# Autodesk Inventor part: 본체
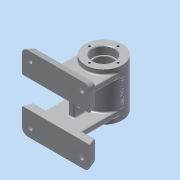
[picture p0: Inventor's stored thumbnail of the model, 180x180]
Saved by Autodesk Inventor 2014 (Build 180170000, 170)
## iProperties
Created: 2016-07
Part Number: 본체
Material: 알루미늄 6061
Document SubType Name: Modeling
Designer: 406-003
Density: 2.71 g/cm^3
Appearance: 알루미늄 - 평지
Author: 406-003
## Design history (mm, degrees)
sketch "스케치1"
  geometry: L1 (100, -55)-(0, -55); L2 (0, -55)-(0, -20); L3 (0, -20)-(100, -20); L4 (100, -20)-(100, -55); L5 (100, 0)-(0, 0); L6 (0, 0)-(0, 55); L7 (0, 55)-(100, 55); L8 (100, 55)-(100, 0); L9 (100, -20)-(100, 0); L10 (0, -20)-(0, 0); 1 further point
  constraints: 20 end point, 4 collinear, 4 parallel, 2 horizontal, 2 perpendicular, 1 coincident, 1 vertical alignment
  dimensions: "d0" = 20 distance between parallel lines of L3 L5; "d1" = 110 distance of L1.end L6.end; "d2" = 35 distance of L1.end L2.end; "d3" = 100 distance of L1.start L1.end
extrude "돌출1" new body sketch "스케치1" distance "d4" = 12; taper "d5" = -20 deg
sketch "스케치3"
  geometry: L1 (-100, 20)-(0, 20); L2 (0, 20)-(0, -20); L3 (0, -20)-(-100, -20); L4 (-100, -20)-(-100, 20); L5 (0, -55)-(-100, -55) reference; L6 (-100, 55)-(0, 55) reference; L7 (-100, -55)-(-100, 55) reference; L8 (0, 55)-(0, -55) reference; 1 further point
  constraints: 8 end point, 2 collinear, 2 parallel, 1 horizontal, 1 perpendicular
  dimensions: "d6" = 35 distance between parallel lines of L5 L3; "d7" = 35 distance between parallel lines of L6 L1
extrude "돌출2" cut sketch "스케치3" distance "d8" = 12; taper "d9" = 0 deg
sketch "스케치4"
  geometry: L1 (0, 0)-(-100, 0) reference; C1 r 27 at (-50, 70); 1 further point
  constraints: 1 centre point, 1 midpoint, 1 vertical alignment
  dimensions: "d10" = 70 distance from line of L1 C1.centre; "d11" = 54 diameter of C1
extrude "돌출3" join sketch "스케치4" stored distance "d12" = 70; taper "d13" = 0 deg
sketch "스케치5"
  geometry: L1 (95.632, -12)-(-4.368, -12) reference; L2 (-4.368, -12)-(0, 0) reference; L3 (0, 0)-(91.265, 0) reference; L4 (91.265, 0)-(95.632, -12) reference; L5 (18.632, 58)-(72.632, 58); L6 (72.632, 58)-(72.632, -12); L7 (72.632, -12)-(18.632, -12); L8 (18.632, -12)-(18.632, 58); 1 further point
  constraints: 8 end point, 2 parallel, 2 vertical, 1 horizontal, 1 horizontal alignment, 1 perpendicular, 1 point on line, 1 other
extrude "돌출4" join sketch "스케치5" distance "d14" = 8; taper "d15" = 0 deg
sketch "스케치6"
  geometry: L1 (95.632, -12)-(-4.368, -12) reference; L2 (0, 0)-(91.265, 0) reference; L3 (91.265, 0)-(95.632, -12) reference; L4 (95.632, -12)-(-4.368, -12) reference; L5 (-4.368, -12)-(0, 0) reference; L6 (18.632, 58)-(72.632, 58); L7 (72.632, 58)-(72.632, -12); L8 (72.632, -12)-(18.632, -12); L9 (18.632, -12)-(18.632, 58); C1 r 27 at (45.632, 58) reference; 1 further point
  constraints: 8 end point, 2 parallel, 2 tangent, 1 coincident, 1 collinear, 1 horizontal, 1 midpoint, 1 perpendicular
extrude "돌출5" join sketch "스케치6" distance "d16" = 8; taper "d17" = 0 deg
node "작업 평면1"
sketch "스케치7"
  geometry: L1 (27, 35)-(-27, 35) reference; C1 r 5 at (0, 13); 2 further points
  constraints: 1 centre point, 1 midpoint, 1 vertical alignment
  dimensions: "d18" = 10 diameter of C1; "d19" = 22 distance of point (0, 35) C1.centre
extrude "돌출6" join sketch "스케치7" distance "d20" = 3; taper "d22" = 0 deg; dims "d21" = 4, "d23" = 0
node "작업 평면3"
sketch "스케치8"
  geometry: L1 (75, -12)-(40, -12) reference; L2 (40, -12)-(40, 31) reference; L3 (40, 31)-(0, 31) reference; L4 (0, 31)-(0, -12) reference; L5 (0, -12)-(-35, -12) reference; L6 (-35, -12)-(-30.632, 0) reference; L7 (-30.632, 0)-(-8, 0) reference; L8 (-8, 0)-(-8, 31) reference; L9 (-8, 31)-(-15, 31) reference; L10 (-15, 31)-(-15, 85) reference; L11 (-15, 85)-(28, 85) reference; L12 (28, 85)-(28, 88) reference; L13 (28, 88)-(38, 88) reference; L14 (38, 88)-(38, 85) reference; L15 (38, 85)-(55, 85) reference; L16 (55, 85)-(55, 31) reference; L17 (55, 31)-(48, 31) reference; L18 (48, 31)-(48, 0) reference; L19 (48, 0)-(70.632, 0) reference; L20 (70.632, 0)-(75, -12) reference; L21 (-15, 58)-(55, 58); L22 (-15, 58)-(-15, 74); L23 (-15, 74)-(-3.3, 74); L24 (-3, 73.7)-(-3, 72); L25 (-3, 72)-(-1, 72); L26 (-1, 72)-(-1, 76); L27 (2, 79)-(38, 79); L28 (41, 76)-(41, 72); L29 (41, 72)-(43, 72); L30 (43, 72)-(43, 73.7); L31 (43.3, 74)-(55, 74); L32 (55, 74)-(55, 58); L33 (55, 58)-(-15, 58); A1 r 0.3 centre (-3.3, 73.7) between (-3, 73.7) and (-3.3, 74); A2 r 0.3 centre (43.3, 73.7) between (43.3, 74) and (43, 73.7); A3 r 3 centre (2, 76) between (2, 79) and (-1, 76); A4 r 3 centre (38, 76) between (41, 76) and (38, 79); 5 further points
  constraints: 26 end point, 10 point on line, 8 point on circle, 8 tangent, 5 parallel, 4 centre point, 4 perpendicular, 3 collinear, 2 equal radius, 2 midpoint
  dimensions: "d24" = 12 distance of L22.end point (-3, 74); "d25" = 42 distance of point (-1, 79) point (41, 79); "d26" = 12 distance of point (43, 74) L31.end; "d27" = 2 distance of L24.end L25.end; "d28" = 32 diameter of L23 L21; "d29" = 28 diameter of L25 L21; "d30" = 32 diameter of L31 L21; "d31" = 42 diameter of L27 L21; "d32" = 0.3 radius of A1; "d33" = 3 radius of A3
  node "절단 모서리 투영3"
sketch "스케치9"
  geometry: L1 (75, -12)-(40, -12) reference; L2 (40, -12)-(40, 31) reference; L3 (40, 31)-(0, 31) reference; L4 (0, 31)-(0, -12) reference; L5 (0, -12)-(-35, -12) reference; L6 (-35, -12)-(-30.632, 0) reference; L7 (-30.632, 0)-(-8, 0) reference; L8 (-8, 0)-(-8, 31) reference; L9 (-8, 31)-(-15, 31) reference; L10 (-15, 31)-(-15, 85) reference; L11 (-15, 85)-(28, 85) reference; L12 (28, 85)-(28, 88) reference; L13 (28, 88)-(38, 88) reference; L14 (38, 88)-(38, 85) reference; L15 (38, 85)-(55, 85) reference; L16 (55, 85)-(55, 31) reference; L17 (55, 31)-(48, 31) reference; L18 (48, 31)-(48, 0) reference; L19 (48, 0)-(70.632, 0) reference; L20 (70.632, 0)-(75, -12) reference; L21 (0, 10)-(40, 10); L22 (40, 10)-(40, 45); L23 (40, 45)-(0, 45); L24 (0, 45)-(0, 10); L25 (12, 20)-(28, 20); L26 (12, 23.5)-(28, 23.5); L27 (28, 16.5)-(12, 16.5); A1 r 3.5 centre (12, 20) between (12, 23.5) and (12, 16.5); A2 r 3.5 centre (28, 20) between (28, 16.5) and (28, 23.5); 3 further points
  constraints: 16 end point, 4 parallel, 4 point on circle, 4 tangent, 2 centre point, 2 midpoint, 1 collinear, 1 horizontal, 1 perpendicular, 1 point on line, 1 vertical alignment
  dimensions: "d34" = 21 distance between parallel lines of L3 L21; "d35" = 35 distance of L23.end L21.start; "d36" = 7 distance between parallel lines of L27 L26; "d37" = 23 dimension on A2 A1; "d38" = 32 distance between parallel lines of L5 L25
extrude "돌출7" join sketch "스케치9" stored distance "d39" = 8; taper "d40" = 0 deg
revolve "회전1" stored, may be unused: angle "d41" = 90 deg
sketch "스케치10"
  geometry: L1 (0, -55)-(-100, -55) reference; L2 (-100, -55)-(-100, -20) reference; 2 further points
  dimensions: "d42" = 12.5 distance from line of L1 point (-87.5, -42.5); "d43" = 12.5 distance from line of L2 point (-87.5, -42.5)
hole "구멍1" sketch "스케치10" at (-87.5, -42.5) diameter "d44" = 6; stored, may be unused: countersink angle "d48" = 90 deg, drill point angle "d50" = 118 deg; dims "d45" = 6, "d46" = 10, "d47" = 4, "d49" = 8
sketch "스케치11" dims "d57" = 42
  geometry: C1 r 16 at (0, 0) reference; C2 r 27 at (0, 0) reference; 3 further points
  constraints: 2 vertical alignment, 1 coincident, 2 other
hole "구멍2" sketch "스케치11" at (0, 21) diameter "d58" = 3.242; stored, may be unused: countersink angle "d62" = 90 deg, drill point angle "d64" = 120 deg; dims "d59" = 8, "d60" = 10, "d61" = 4, "d63" = 10
hole "구멍3" diameter "d70" = 5.188; stored, may be unused: countersink angle "d74" = 90 deg, drill point angle "d76" = 120 deg; dims "d68" = 10, "d69" = 10, "d71" = 30, "d72" = 10, "d73" = 4, "d75" = 30
node "작업 평면4"
sketch "스케치12"
  geometry: L1 (0, 0)-(-15.898, -25.441); L2 (4, -26.702)-(4, -34.5) reference; L3 (4, -34.5)-(-4, -34.5) reference; L4 (-4, -34.5)-(-4, -26.702) reference; L5 (4, -41.5)-(4, -48) reference; L6 (4, -48)-(-4, -48) reference; L7 (-4, -48)-(-4, -41.5) reference; L8 (-4, -41.5)-(4, -41.5) reference; L9 (0, 0)-(0, -21); L10 (-15.898, -25.441)-(-10.809, -28.621); L11 (-10.809, -28.621)-(-7.63, -23.533); L12 (-7.63, -23.533)-(-12.718, -20.353); L13 (-15.898, -25.441)-(-12.718, -20.353); A1 r 27 centre (0, 0) between (4, -26.702) and (-4, -26.702) reference; 2 further points
  constraints: 12 end point, 4 perpendicular, 1 coincident, 1 collinear, 1 point on line, 1 vertical alignment, 1 other
  dimensions: "d78" = 30 distance of L1.start L1.end; "d79" = 328 deg dimension on L9 L1; "d80" = 6 distance of L1.end L10.end; "d81" = 6 distance of L10.end L11.end
revolve "회전2" sketch "스케치12" stored, may be unused: angle "d82" = 90 deg
hole "구멍4" diameter "d85" = 5.188; stored, may be unused: countersink angle "d89" = 90 deg, drill point angle "d91" = 120 deg; dims "d83" = 10, "d84" = 10, "d86" = 30, "d87" = 10, "d88" = 4, "d90" = 30
fillet "모깎기1" dims "d92" = 2
fillet "모깎기2" dims "d93" = 2
fillet "모깎기3" dims "d94" = 2
fillet "모깎기4" dims "d95" = 2
fillet "모깎기5" dims "d98" = 2
fillet "모깎기6" dims "d99" = 2
node "작업 평면5"
sketch "스케치16"
  geometry: L1 (27, 35)-(-27, 35) reference; 2 further points
  constraints: 1 other
  dimensions: "d100" = 35 distance from line of L1 point (0, 0); "d101" = 27 horizontal distance of point (0, 0) L1.start
feature "엠보싱1" sketch "스케치16" dims "d3" = 100, "d102" = 0.5, "d103" = 0
fillet "모깎기7" dims "d104" = 5, "d105" = 10
fillet "모깎기8" dims "d106" = 5, "d107" = 10
fillet "모깎기9" dims "d108" = 5, "d109" = 10
fillet "모깎기10" dims "d110" = 5, "d111" = 10
chamfer "모따기1" distance "d112" = 1; stored, may be unused: second distance "d113" = 2, angle "d114" = 45 deg
node "솔리드1"
pattern_linear "직사각형 패턴1" dims "d53" = 75, "d56" = 85
pattern_circular "원형 패턴1" dims angle "d66" = 360 deg
mirror "대칭1"
node "절단 모서리 투영1"
node "절단 모서리 투영2"
node "절단 모서리 투영4"
node "절단 모서리 투영5"
other parameters: "d77" = -35
